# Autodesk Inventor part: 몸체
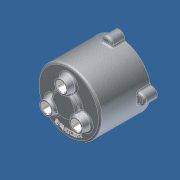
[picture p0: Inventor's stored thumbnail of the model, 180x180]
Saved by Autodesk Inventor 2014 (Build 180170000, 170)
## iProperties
Created: 2012-05
Part Number: 몸체
Document SubType Name: 모델링
Designer: SeoGD™
Material: 알루미늄 6061
Appearance: 알루미늄 - 평지
Mass: 175.481 g
Surface Area: 687.661 cm^2
Volume: 175.481 cm^3
Density: 1 g/cm^3
변환 표준: STEP AP214IS
파일 이름: C:\Users\SeoGD\Desktop\?쒗뿕\紐몄껜.stp
전처리기: Build: 253, Release: 2010 SP1 - Date: Wed 07/29/2009
전송 단위: 밀리미터
불확실성: 0.01
Author: SeoGD™
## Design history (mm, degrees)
sketch "스케치2"
  geometry: C1 r 50 at (0, 0); 1 further point
  constraints: 1 centre point, 1 coincident
  dimensions: "d9" = 100 diameter of C1
extrude "돌출2" new body sketch "스케치2" distance "d10" = 80; taper "d11" = 0 deg
feature "쉘1" dims "d12" = 5
sketch "스케치3" dims "d13" = 55
  geometry: C1 r 7.5 at (0, 27.5); C2 r 12.5 at (0, 27.5); 2 further points
  constraints: 2 centre point, 2 coincident, 2 vertical alignment, 2 other
  dimensions: "d14" = 15 diameter of C1; "d15" = 25 diameter of C2
extrude "돌출3" join sketch "스케치3" distance "d16" = 12; taper "d17" = -10 deg
hole "구멍2" diameter "d20" = 15; stored, may be unused: countersink angle "d24" = 90 deg, drill point angle "d26" = 118 deg; dims "d18" = 10, "d19" = 10, "d21" = 6, "d22" = 4, "d23" = 2, "d25" = 15
chamfer "모따기1" distance "d27" = 1; stored, may be unused: second distance "d28" = 2, angle "d29" = 45 deg
sketch "스케치4"
  geometry: L1 (0, 0)-(0, 88); L2 (0, 70)-(13.16, 70); L3 (-45, 75)-(45, 75) reference; L4 (-50, 80)-(50, 80) reference; L5 (13.16, 70)-(14.5, 75); L6 (20, 80)-(20, 88); L7 (20, 88)-(0, 88); L8 (20, 80)-(14.5, 75)
  constraints: 12 end point, 3 point on line, 2 perpendicular, 1 vertical
  dimensions: "d34" = 40 diameter of L6 L1; "d35" = 105 deg angle of L5 L3; "d36" = 5 distance between parallel lines of L2 L3; "d37" = 8 distance between parallel lines of L7 L4; "d51" = 29 diameter of L5.end L1
revolve "회전1" sketch "스케치4" stored, may be unused: angle "d38" = 90 deg
hole "구멍3" diameter "d41" = 15; stored, may be unused: countersink angle "d45" = 90 deg, drill point angle "d47" = 0 deg; dims "d39" = 10, "d40" = 10, "d42" = 6, "d43" = 22, "d44" = 13, "d46" = 15
chamfer "모따기2" distance "d48" = 1; stored, may be unused: second distance "d49" = 2, angle "d50" = 45 deg
fillet "모깎기1" dims "d52" = 3
fillet "모깎기2" dims "d53" = 3, "d72" = 0.2
sketch "스케치5"
  geometry: A1 r 50 centre (0, 0) between (50, 0) and (-8.074, 49.344) reference; A2 r 8.5 centre (0, 52) between (8.074, 49.344) and (-8.074, 49.344); 1 further point
  constraints: 5 point on circle, 1 centre point, 1 horizontal alignment
  dimensions: "d54" = 90 deg dimension on point (0, 0) A2.centre A1.start; "d55" = 52 distance of A2.centre point (0, 0); "d56" = 17 diameter of A2
extrude "돌출4" join sketch "스케치5" distance "d57" = 20; taper "d58" = 0 deg
fillet "모깎기3" dims "d59" = 3
hole "구멍4" diameter "d62" = 4.134; stored, may be unused: countersink angle "d66" = 90 deg, drill point angle "d68" = 118 deg; dims "d60" = 10, "d61" = 10, "d63" = 12, "d64" = 22, "d65" = 13, "d67" = 15
sketch "스케치6"
  geometry: C1 r 47 at (0, 0) reference; C2 r 42.5 at (0, 0); 1 further point
  constraints: 1 centre point, 1 coincident, 1 other
  dimensions: "d73" = 85 diameter of C2
feature "엠보싱1" sketch "스케치6" dims "d74" = 1, "d75" = 0
node "솔리드1"
node "솔리드 본체"
node "곡면 본체"
pattern_circular "원형 패턴1" dims "d31" = 360 deg
pattern_circular "원형 패턴2" dims "d70" = 360 deg
node "솔리드2"
